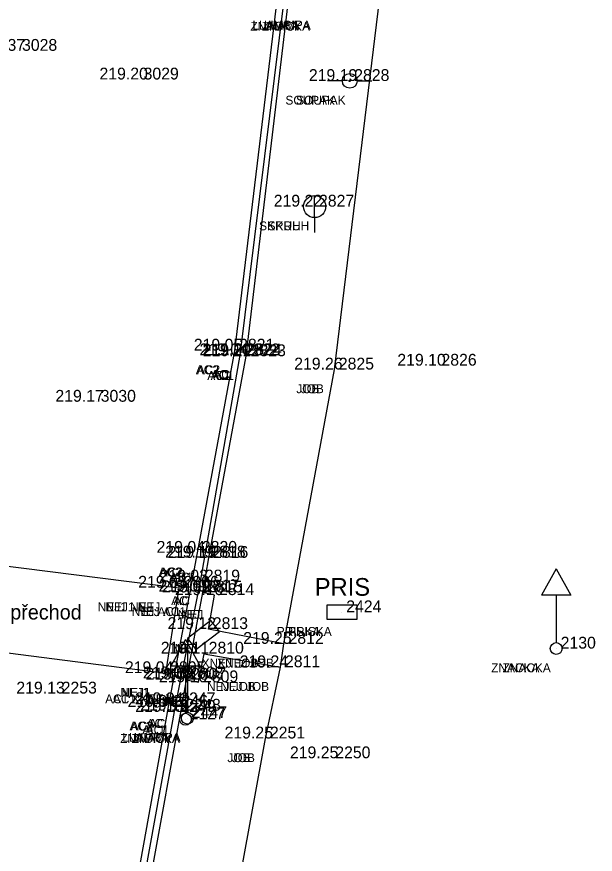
# Model space of a CAD drawing. Extents: x -471047 to -470889, y -1102859 to -1102000.
# Drawn here: x -470928.21 to -470908.65, y -1102212.58 to -1102184.25 of the extents above; entities that cross this region are included whole.
import ezdxf

# ---------------------------------------------------------------- set-up
doc = ezdxf.new("R2010")
doc.units = 0
for name, color, linetype in [('Vrstva 1', 7, 'Continuous'), ('Vrstva 11', 7, 'Continuous'), ('Vrstva 19', 7, 'Continuous'), ('Vrstva 22', 7, 'Continuous'), ('Vrstva 23', 7, 'Continuous'), ('Vrstva 25', 7, 'Continuous'), ('Vrstva 34', 7, 'Continuous'), ('Vrstva 35', 7, 'Continuous'), ('Vrstva 36', 7, 'Continuous'), ('Vrstva 38', 7, 'Continuous'), ('Vrstva 5', 7, 'Continuous'), ('Vrstva 7', 7, 'Continuous'), ('Vrstva 8', 7, 'Continuous')]:
    doc.layers.add(name, color=color, linetype=linetype)

msp = doc.modelspace()

# ---------------------------------------------------------------- linework, layer by layer
at = {"layer": 'Vrstva 1'}
for points in [[(-471040.344, -1102858.385), (-471031.676, -1102846.187), (-471026.357, -1102838.629), (-471023.212, -1102833.975), (-471019.21, -1102827.465), (-471016.861, -1102823.272), (-471013.099, -1102815.912), (-471010.824, -1102810.955), (-471007.329, -1102802.292), (-471005.34, -1102796.515), (-471002.842, -1102787.838), (-471001.3, -1102780.997), (-471000.19, -1102774.713), (-470999.247, -1102768.204), (-470998.794, -1102764.784), (-470997.199, -1102751.812), (-470994.899, -1102732.807), (-470992.551, -1102713.262), (-470990.326, -1102694.887), (-470988.122, -1102676.57), (-470985.812, -1102657.305), (-470983.537, -1102638.407), (-470981.386, -1102620.622), (-470979.843, -1102608.014), (-470976.377, -1102579.253), (-470972.945, -1102550.69), (-470970.475, -1102530.206), (-470967.905, -1102508.801), (-470965.053, -1102485.131), (-470962.734, -1102465.9), (-470960.173, -1102444.812), (-470957.795, -1102425.103), (-470954.965, -1102401.839), (-470953.834, -1102392.574), (-470952.33, -1102379.985), (-470950.744, -1102366.853), (-470948.978, -1102352.106), (-470947.037, -1102335.844), (-470944.949, -1102318.462), (-470944.013, -1102310.745), (-470942.39, -1102297.267), (-470939.519, -1102273.45), (-470937.593, -1102257.43), (-470936.064, -1102244.81), (-470934.114, -1102228.634), (-470931.621, -1102207.856), (-470929.536, -1102190.857), (-470926.572, -1102166.31), (-470924.91, -1102152.663), (-470923.413, -1102140.333), (-470921.923, -1102127.669), (-470921.155, -1102120.084), (-470920.446, -1102109.574), (-470919.912, -1102099.137), (-470919.63, -1102088.981), (-470919.523, -1102081.193), (-470919.563, -1102070.395), (-470919.714, -1102064.236), (-470920.134, -1102054.704), (-470920.462, -1102047.615), (-470920.599, -1102044.52), (-470920.743, -1102041.873), (-470921.125, -1102034.455), (-470921.774, -1102030.337), (-470922.418, -1102027.787), (-470923.734, -1102023.93), (-470924.872, -1102021.434), (-470926.752, -1102018.182), (-470927.953, -1102016.45), (-470929.616, -1102014.424), (-470932.252, -1102011.756), (-470935.111, -1102009.425), (-470938.391, -1102007.371), (-470942.651, -1102005.401)], [(-471041.328, -1102857.18), (-471032.144, -1102844.242), (-471027.583, -1102837.763), (-471024.388, -1102833.028), (-471020.451, -1102826.6), (-471018.089, -1102822.378), (-471014.542, -1102815.445), (-471012.233, -1102810.418), (-471009.247, -1102803.108), (-471006.795, -1102796.098), (-471004.315, -1102787.532), (-471002.782, -1102780.723), (-471001.674, -1102774.458), (-471000.75, -1102768.095), (-471000.28, -1102764.601), (-470998.692, -1102751.741), (-470996.378, -1102732.635), (-470994.028, -1102713.058), (-470991.808, -1102694.749), (-470989.616, -1102676.447), (-470987.284, -1102657.013), (-470985.031, -1102638.272), (-470982.87, -1102620.431), (-470981.334, -1102607.933), (-470977.881, -1102579.263), (-470974.429, -1102550.492), (-470971.964, -1102530.054), (-470969.391, -1102508.607), (-470966.54, -1102484.984), (-470964.231, -1102465.853), (-470961.679, -1102444.752), (-470959.304, -1102425.078), (-470956.455, -1102401.634), (-470955.339, -1102392.489), (-470953.812, -1102379.71), (-470952.249, -1102366.808), (-470950.479, -1102352.023), (-470948.536, -1102335.868), (-470946.426, -1102318.233), (-470945.493, -1102310.531), (-470943.864, -1102297.013), (-470940.984, -1102273.071), (-470939.078, -1102257.195), (-470937.559, -1102244.684), (-470935.592, -1102228.353), (-470933.101, -1102207.653), (-470931.011, -1102190.57), (-470928.046, -1102166.021), (-470926.409, -1102152.578), (-470924.898, -1102140.121), (-470923.427, -1102127.544), (-470922.647, -1102119.826), (-470921.919, -1102109.229), (-470921.42, -1102099.134), (-470921.127, -1102089.016), (-470921.023, -1102081.453), (-470921.061, -1102070.468), (-470921.209, -1102064.314), (-470921.666, -1102053.966), (-470922.156, -1102043.345), (-470922.299, -1102039.934), (-470922.637, -1102034.36), (-470923.091, -1102031.241), (-470923.847, -1102028.247), (-470925.083, -1102024.594), (-470926.222, -1102022.086), (-470928.04, -1102018.943), (-470929.138, -1102017.357), (-470930.929, -1102015.175), (-470933.062, -1102013.049), (-470936.379, -1102010.368), (-470939.169, -1102008.662), (-470942.899, -1102006.906), (-470945.661, -1102005.908)], [(-471043.557, -1102855.955), (-471035.129, -1102844.026), (-471029.872, -1102836.499), (-471026.577, -1102831.578), (-471022.675, -1102825.415), (-471020.123, -1102821.053), (-471016.667, -1102814.59), (-471014.208, -1102809.45), (-471011.177, -1102802.451), (-471008.55, -1102795.333), (-471006.082, -1102787.209), (-471004.464, -1102780.376), (-471003.265, -1102774.167), (-471002.327, -1102767.948), (-471001.636, -1102762.527), (-471000.297, -1102751.605), (-470997.959, -1102732.524), (-470995.602, -1102712.802), (-470993.412, -1102694.623), (-470991.21, -1102676.17), (-470988.891, -1102656.857), (-470986.625, -1102638.083), (-470984.455, -1102620.195), (-470982.936, -1102607.733), (-470979.497, -1102579.223), (-470976.023, -1102550.279), (-470973.554, -1102529.822), (-470970.991, -1102508.497), (-470968.146, -1102484.787), (-470965.835, -1102465.72), (-470963.284, -1102444.529), (-470960.91, -1102424.942), (-470958.043, -1102401.343), (-470956.946, -1102392.356), (-470955.396, -1102379.408), (-470953.851, -1102366.636), (-470952.049, -1102351.733), (-470950.124, -1102335.611), (-470948.034, -1102318.083), (-470947.094, -1102310.328), (-470945.421, -1102296.51), (-470942.58, -1102272.848), (-470940.675, -1102256.948), (-470939.176, -1102244.526), (-470937.187, -1102228.174), (-470934.708, -1102207.467), (-470932.621, -1102190.433), (-470929.634, -1102165.778), (-470928.004, -1102152.415), (-470926.45, -1102139.595), (-470925.003, -1102127.418), (-470924.249, -1102119.695), (-470923.515, -1102109.093), (-470923.018, -1102099.069), (-470922.711, -1102088.911), (-470922.643, -1102081.356), (-470922.797, -1102070.414), (-470923.018, -1102064.454), (-470923.52, -1102053.203), (-470923.823, -1102047.529), (-470924.123, -1102041.506), (-470924.462, -1102037.486), (-470924.934, -1102031.904), (-470925.664, -1102028.672), (-470926.771, -1102025.506), (-470927.959, -1102022.914), (-470929.674, -1102020.028), (-470930.76, -1102018.498), (-470932.447, -1102016.478), (-470935.215, -1102013.816), (-470937.644, -1102011.98), (-470940.381, -1102010.371), (-470943.968, -1102008.669), (-470947.145, -1102007.524), (-470950.874, -1102006.74)], [(-471044.756, -1102855.056), (-471036.376, -1102843.177), (-471031.167, -1102835.741), (-471027.859, -1102830.8), (-471023.934, -1102824.593), (-471021.43, -1102820.312), (-471018.011, -1102813.91), (-471015.536, -1102808.75), (-471012.578, -1102801.897), (-471009.95, -1102794.77), (-471007.561, -1102786.914), (-471005.936, -1102780.074), (-471004.727, -1102773.818), (-471003.828, -1102767.827), (-471003.121, -1102762.345), (-471001.787, -1102751.467), (-470999.446, -1102732.348), (-470997.073, -1102712.539), (-470994.902, -1102694.521), (-470992.696, -1102676.023), (-470990.376, -1102656.68), (-470988.131, -1102638.071), (-470985.947, -1102620.018), (-470984.417, -1102607.512), (-470980.993, -1102579.08), (-470977.514, -1102550.137), (-470975.048, -1102529.649), (-470972.488, -1102508.37), (-470969.618, -1102484.508), (-470967.34, -1102465.669), (-470964.767, -1102444.39), (-470962.402, -1102424.781), (-470959.534, -1102401.193), (-470958.432, -1102392.151), (-470956.883, -1102379.208), (-470955.335, -1102366.424), (-470953.535, -1102351.506), (-470951.606, -1102335.399), (-470949.519, -1102317.94), (-470948.575, -1102310.159), (-470946.889, -1102296.144), (-470944.056, -1102272.618), (-470942.139, -1102256.659), (-470940.657, -1102244.341), (-470938.638, -1102227.749), (-470936.19, -1102207.298), (-470934.102, -1102190.255), (-470931.124, -1102165.639), (-470929.492, -1102152.254), (-470927.915, -1102139.252), (-470926.46, -1102127.103), (-470925.74, -1102119.604), (-470925.012, -1102108.913), (-470924.523, -1102099.054), (-470924.217, -1102088.866), (-470924.148, -1102081.334), (-470924.301, -1102070.391), (-470924.518, -1102064.43), (-470924.97, -1102054.435), (-470925.588, -1102041.569), (-470925.963, -1102035.313), (-470926.405, -1102032.225), (-470927.078, -1102029.198), (-470928.123, -1102026.148), (-470929.318, -1102023.558), (-470930.84, -1102020.97), (-470931.868, -1102019.515), (-470933.443, -1102017.605), (-470936.26, -1102014.885), (-470938.429, -1102013.255), (-470941.213, -1102011.639), (-470944.847, -1102009.927), (-470947.723, -1102008.912), (-470951.444, -1102008.161), (-470954.511, -1102007.931), (-470957.895, -1102008.041)]]:
    msp.add_spline(points, degree=3, dxfattribs=at)
at = {"layer": 'Vrstva 11'}
for p, q in [((-470917.2, -1102186.415), (-470917.7, -1102186.415)), ((-470916.7, -1102186.415), (-470916.2, -1102186.415))]:
    msp.add_line(p, q, dxfattribs=at)
for radius in [0.25, 0.025]:
    msp.add_circle((-470916.95, -1102186.415), radius, dxfattribs=at)
at = {"layer": 'Vrstva 19'}
for p, q in [((-470909.972, -1102202.918), (-470910.472, -1102203.818)), ((-470909.972, -1102202.918), (-470909.472, -1102203.818)), ((-470909.472, -1102203.818), (-470910.472, -1102203.818)), ((-470909.972, -1102203.818), (-470909.972, -1102205.418)), ((-470922.506, -1102205.309), (-470923.006, -1102206.209)), ((-470922.506, -1102205.309), (-470922.006, -1102206.209)), ((-470922.006, -1102206.209), (-470923.006, -1102206.209)), ((-470922.506, -1102206.209), (-470922.506, -1102207.809))]:
    msp.add_line(p, q, dxfattribs=at)
for centre in [(-470909.972, -1102205.618), (-470922.506, -1102208.009)]:
    msp.add_circle(centre, 0.2, dxfattribs=at)
at = {"layer": 'Vrstva 23'}
for p, q in [((-470921.644, -1102204.669), (-470922.439, -1102205.274)), ((-470921.354, -1102205.046), (-470921.644, -1102204.669)), ((-470922.439, -1102205.274), (-470922.439, -1102207.774)), ((-470922.439, -1102205.274), (-470922.152, -1102205.652)), ((-470922.152, -1102205.652), (-470921.354, -1102205.046))]:
    msp.add_line(p, q, dxfattribs=at)
msp.add_lwpolyline([(-470917.716, -1102204.136), (-470916.716, -1102204.136), (-470916.716, -1102204.636), (-470917.716, -1102204.636)], close=True, dxfattribs=at)
msp.add_circle((-470922.439, -1102207.974), 0.2, dxfattribs=at)
at = {"layer": 'Vrstva 25'}
for q in [(-470918.141, -1102190.292), (-470918.141, -1102191.542)]:
    msp.add_line((-470918.141, -1102191.042), q, dxfattribs=at)
msp.add_circle((-470918.141, -1102190.667), 0.375, dxfattribs=at)
at = {"layer": 'Vrstva 34'}
for p, q in [((-470928.18, -1102185.4), (-470928.18, -1102185.4)), ((-470924.07, -1102186.37), (-470924.07, -1102186.37)), ((-470916.95, -1102186.42), (-470916.95, -1102186.42)), ((-470918.14, -1102190.67), (-470918.14, -1102190.67)), ((-470920.84, -1102195.54), (-470920.84, -1102195.54)), ((-470920.65, -1102195.7), (-470920.65, -1102195.7)), ((-470920.59, -1102195.7), (-470920.59, -1102195.7)), ((-470920.45, -1102195.73), (-470920.45, -1102195.73)), ((-470917.47, -1102196.18), (-470917.47, -1102196.18)), ((-470914, -1102196.05), (-470914, -1102196.05)), ((-470925.52, -1102197.27), (-470925.52, -1102197.27)), ((-470922.1, -1102202.38), (-470922.1, -1102202.38)), ((-470921.81, -1102202.54), (-470921.81, -1102202.54)), ((-470921.72, -1102202.55), (-470921.72, -1102202.55)), ((-470922.72, -1102203.56), (-470922.72, -1102203.56)), ((-470922, -1102203.35), (-470922, -1102203.35)), ((-470922.03, -1102203.69), (-470922.03, -1102203.69)), ((-470921.92, -1102203.72), (-470921.92, -1102203.72)), ((-470921.52, -1102203.81), (-470921.52, -1102203.81)), ((-470917.22, -1102204.39), (-470917.22, -1102204.39)), ((-470921.73, -1102204.96), (-470921.73, -1102204.96)), ((-470919.17, -1102205.46), (-470919.17, -1102205.46)), ((-470921.87, -1102205.79), (-470921.87, -1102205.79)), ((-470909.97, -1102205.62), (-470909.97, -1102205.62)), ((-470919.29, -1102206.25), (-470919.29, -1102206.25)), ((-470923.17, -1102206.45), (-470923.17, -1102206.45)), ((-470922.56, -1102206.63), (-470922.56, -1102206.63)), ((-470922.47, -1102206.67), (-470922.47, -1102206.67)), ((-470922.06, -1102206.76), (-470922.06, -1102206.76)), ((-470926.84, -1102207.14), (-470926.84, -1102207.14)), ((-470922.83, -1102207.5), (-470922.83, -1102207.5)), ((-470923.08, -1102207.59), (-470923.08, -1102207.59)), ((-470922.82, -1102207.76), (-470922.82, -1102207.76)), ((-470922.65, -1102207.72), (-470922.65, -1102207.72)), ((-470922.51, -1102208.01), (-470922.51, -1102208.01)), ((-470922.44, -1102207.97), (-470922.44, -1102207.97)), ((-470919.8, -1102208.66), (-470919.8, -1102208.66)), ((-470917.59, -1102209.33), (-470917.59, -1102209.33))]:
    msp.add_line(p, q, dxfattribs=at)
at = {"layer": 'Vrstva 5'}
for p, q in [((-470920.841, -1102195.544), (-470919.213, -1102182.137)), ((-470922.096, -1102202.379), (-470920.841, -1102195.544)), ((-470923.084, -1102207.586), (-470922.096, -1102202.379)), ((-470926.14, -1102224.666), (-470923.084, -1102207.586))]:
    msp.add_line(p, q, dxfattribs=at)
at = {"layer": 'Vrstva 7'}
for p, q in [((-470920.454, -1102195.728), (-470918.838, -1102182.155)), ((-470921.718, -1102202.546), (-470920.454, -1102195.728)), ((-470921.916, -1102203.718), (-470921.718, -1102202.546)), ((-470922.467, -1102206.671), (-470921.916, -1102203.718)), ((-470922.651, -1102207.718), (-470922.467, -1102206.671)), ((-470925.762, -1102224.737), (-470922.651, -1102207.718))]:
    msp.add_line(p, q, dxfattribs=at)
at = {"layer": 'Vrstva 8'}
for p, q in [((-470917.47, -1102196.176), (-470915.653, -1102181.23)), ((-470920.651, -1102195.695), (-470918.971, -1102182.117)), ((-470921.996, -1102203.345), (-470920.651, -1102195.695)), ((-470919.175, -1102205.463), (-470917.47, -1102196.176)), ((-470930.332, -1102202.597), (-470922.724, -1102203.56)), ((-470923.171, -1102206.453), (-470922.724, -1102203.56)), ((-470922.83, -1102207.5), (-470921.996, -1102203.345)), ((-470921.524, -1102203.813), (-470921.916, -1102203.718)), ((-470921.731, -1102204.962), (-470921.524, -1102203.813)), ((-470919.175, -1102205.463), (-470921.731, -1102204.962)), ((-470930.605, -1102205.495), (-470923.171, -1102206.453)), ((-470919.294, -1102206.253), (-470919.175, -1102205.463)), ((-470922.061, -1102206.76), (-470921.87, -1102205.792)), ((-470921.87, -1102205.792), (-470919.294, -1102206.253)), ((-470919.801, -1102208.66), (-470919.294, -1102206.253)), ((-470922.467, -1102206.671), (-470922.061, -1102206.76)), ((-470925.95, -1102224.774), (-470922.83, -1102207.5)), ((-470922.725, -1102224.731), (-470919.801, -1102208.66))]:
    msp.add_line(p, q, dxfattribs=at)

# ---------------------------------------------------------------- texts
at = {"layer": 'Vrstva 22'}
msp.add_text('přechod', height=0.5, dxfattribs=at).set_placement((-470928.43, -1102204.636))
at = {"layer": 'Vrstva 23'}
msp.add_text('PRIS', height=0.6, dxfattribs=at).set_placement((-470918.136, -1102203.834))
at = {"layer": 'Vrstva 35'}
for s, p in [('ZNACKA', (-470920.31, -1102184.72)), ('LLAMPA', (-470920.24, -1102184.68)), ('ZNACKA', (-470919.924, -1102184.72)), ('LLAMPA', (-470919.854, -1102184.68)), ('SOUPAK', (-470919.125, -1102187.22)), ('SOUPAK', (-470918.764, -1102187.22)), ('SKRUH', (-470920.015, -1102191.47)), ('SKRUH', (-470919.729, -1102191.47)), ('AC2', (-470922.156, -1102196.34)), ('AC2', (-470922.115, -1102196.34)), ('AC1', (-470921.767, -1102196.53)), ('AC1', (-470921.65, -1102196.53)), ('AC', (-470921.639, -1102196.5)), ('AC', (-470921.564, -1102196.5)), ('JOB', (-470918.759, -1102196.98)), ('JOB', (-470918.609, -1102196.98)), ('AC2', (-470923.416, -1102203.18)), ('AC2', (-470923.375, -1102203.18)), ('AC1', (-470923.037, -1102203.35)), ('AC1', (-470922.92, -1102203.35)), ('AC', (-470922.989, -1102204.15)), ('AC', (-470922.914, -1102204.15)), ('NEJ1 NEJ', (-470925.47, -1102204.36)), ('NEJ1 NEJ', (-470925.209, -1102204.36)), ('NEJ AC1', (-470924.32, -1102204.52)), ('NEJ AC1', (-470924.137, -1102204.52)), ('NEJ', (-470922.77, -1102204.61)), ('NEJ', (-470922.659, -1102204.61)), ('PRISKA', (-470919.42, -1102205.19)), ('PRISKA', (-470919.034, -1102205.19)), ('NEJ', (-470922.98, -1102205.76)), ('NEJ', (-470922.869, -1102205.76)), ('XNEJ JOB', (-470921.959, -1102206.26)), ('XNEJ JOB', (-470921.434, -1102206.26)), ('ZNACKA', (-470912.17, -1102206.42)), ('ZNACKA', (-470911.784, -1102206.42)), ('NEJ', (-470923.12, -1102206.59)), ('NEJ', (-470923.009, -1102206.59)), ('NEJ1', (-470924.712, -1102207.25)), ('NEJ1', (-470924.67, -1102207.25)), ('NEJ JOB', (-470921.779, -1102207.05)), ('NEJ JOB', (-470921.329, -1102207.05)), ('AC1 XNEJ', (-470925.22, -1102207.47)), ('AC1 XNEJ', (-470924.959, -1102207.47)), ('NEJ', (-470923.31, -1102207.56)), ('NEJ', (-470923.199, -1102207.56)), ('AC2', (-470924.396, -1102208.39)), ('AC2', (-470924.355, -1102208.39)), ('AC', (-470923.819, -1102208.3)), ('AC', (-470923.744, -1102208.3)), ('AC1', (-470923.967, -1102208.52)), ('AC1', (-470923.85, -1102208.52)), ('ZNACKA', (-470924.71, -1102208.81)), ('LLAMPA', (-470924.64, -1102208.77)), ('ZNACKA', (-470924.324, -1102208.81)), ('LLAMPA', (-470924.254, -1102208.77)), ('JOB', (-470921.089, -1102209.46)), ('JOB', (-470920.939, -1102209.46))]:
    msp.add_text(s, height=0.3, dxfattribs=at).set_placement(p)
at = {"layer": 'Vrstva 36'}
for s, p in [(' 3028', (-470928.18, -1102185.4)), (' 3029', (-470924.07, -1102186.37)), (' 2828', (-470916.95, -1102186.42)), (' 2827', (-470918.14, -1102190.67)), (' 2821', (-470920.84, -1102195.54)), (' 2822', (-470920.65, -1102195.7)), (' 2824', (-470920.59, -1102195.7)), (' 2823', (-470920.45, -1102195.73)), (' 2826', (-470914, -1102196.05)), (' 2825', (-470917.47, -1102196.18)), (' 3030', (-470925.52, -1102197.27)), (' 2820', (-470922.1, -1102202.38)), (' 2818', (-470921.81, -1102202.54)), (' 2816', (-470921.72, -1102202.55)), (' 2819', (-470922, -1102203.35)), (' 2806', (-470922.72, -1102203.56)), (' 2817', (-470922.03, -1102203.69)), (' 2815', (-470921.92, -1102203.72)), (' 2814', (-470921.52, -1102203.81)), (' 2424', (-470917.22, -1102204.39)), (' 2813', (-470921.73, -1102204.96)), (' 2812', (-470919.17, -1102205.46)), (' 2130', (-470909.97, -1102205.62)), (' 2810', (-470921.87, -1102205.79)), (' 2811', (-470919.29, -1102206.25)), (' 2805', (-470923.17, -1102206.45)), (' 2808', (-470922.56, -1102206.63)), (' 2807', (-470922.47, -1102206.67)), (' 2809', (-470922.06, -1102206.76)), (' 2253', (-470926.84, -1102207.14)), (' 2246', (-470923.08, -1102207.59)), (' 2247', (-470922.83, -1102207.5)), (' 2249', (-470922.82, -1102207.76)), (' 2248', (-470922.65, -1102207.72)), (' 2447', (-470922.44, -1102207.97)), (' 2127', (-470922.51, -1102208.01)), (' 2251', (-470919.8, -1102208.66)), (' 2250', (-470917.59, -1102209.33))]:
    msp.add_text(s, height=0.4, dxfattribs=at).set_placement(p)
at = {"layer": 'Vrstva 38'}
for s, p in [('219.37 ', (-470929.563, -1102185.4)), ('219.20 ', (-470925.413, -1102186.37)), ('219.19 ', (-470918.334, -1102186.42)), ('219.22 ', (-470919.521, -1102190.67)), ('219.05 ', (-470922.224, -1102195.54)), ('219.04 ', (-470922.032, -1102195.7)), ('219.20 ', (-470921.933, -1102195.7)), ('219.21 ', (-470921.92, -1102195.73)), ('219.10 ', (-470915.343, -1102196.05)), ('219.26 ', (-470918.83, -1102196.18)), ('219.17 ', (-470926.903, -1102197.27)), ('219.04 ', (-470923.482, -1102202.38)), ('219.19 ', (-470923.194, -1102202.54)), ('219.19 ', (-470923.104, -1102202.55)), ('219.03 ', (-470923.383, -1102203.35)), ('219.05 ', (-470924.104, -1102203.56)), ('219.09 ', (-470923.414, -1102203.69)), ('219.09 ', (-470923.304, -1102203.72)), ('219.10 ', (-470922.863, -1102203.81)), ('219.12 ', (-470923.111, -1102204.96)), ('219.25 ', (-470920.554, -1102205.46)), ('219.11 ', (-470923.34, -1102205.79)), ('219.24 ', (-470920.672, -1102206.25)), ('219.04 ', (-470924.552, -1102206.45)), ('219.08 ', (-470923.944, -1102206.63)), ('219.08 ', (-470923.854, -1102206.67)), ('219.10 ', (-470923.403, -1102206.76)), ('219.13 ', (-470928.223, -1102207.14)), ('219.04 ', (-470924.462, -1102207.59)), ('219.04 ', (-470924.212, -1102207.5)), ('219.18 ', (-470924.204, -1102207.76)), ('219.19 ', (-470924.034, -1102207.72)), ('219.25 ', (-470921.184, -1102208.66)), ('219.25 ', (-470918.974, -1102209.33))]:
    msp.add_text(s, height=0.4, dxfattribs=at).set_placement(p)

doc.saveas('drawing.dxf')
